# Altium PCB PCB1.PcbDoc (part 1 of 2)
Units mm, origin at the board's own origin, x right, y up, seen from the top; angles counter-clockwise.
Board outline 100 x 72 mm, 4 copper layers (Top Layer, Ground, Power, Bottom Layer), stack 1.562 mm thick; 122 components, 105 nets, 454 pads, 324 vias.
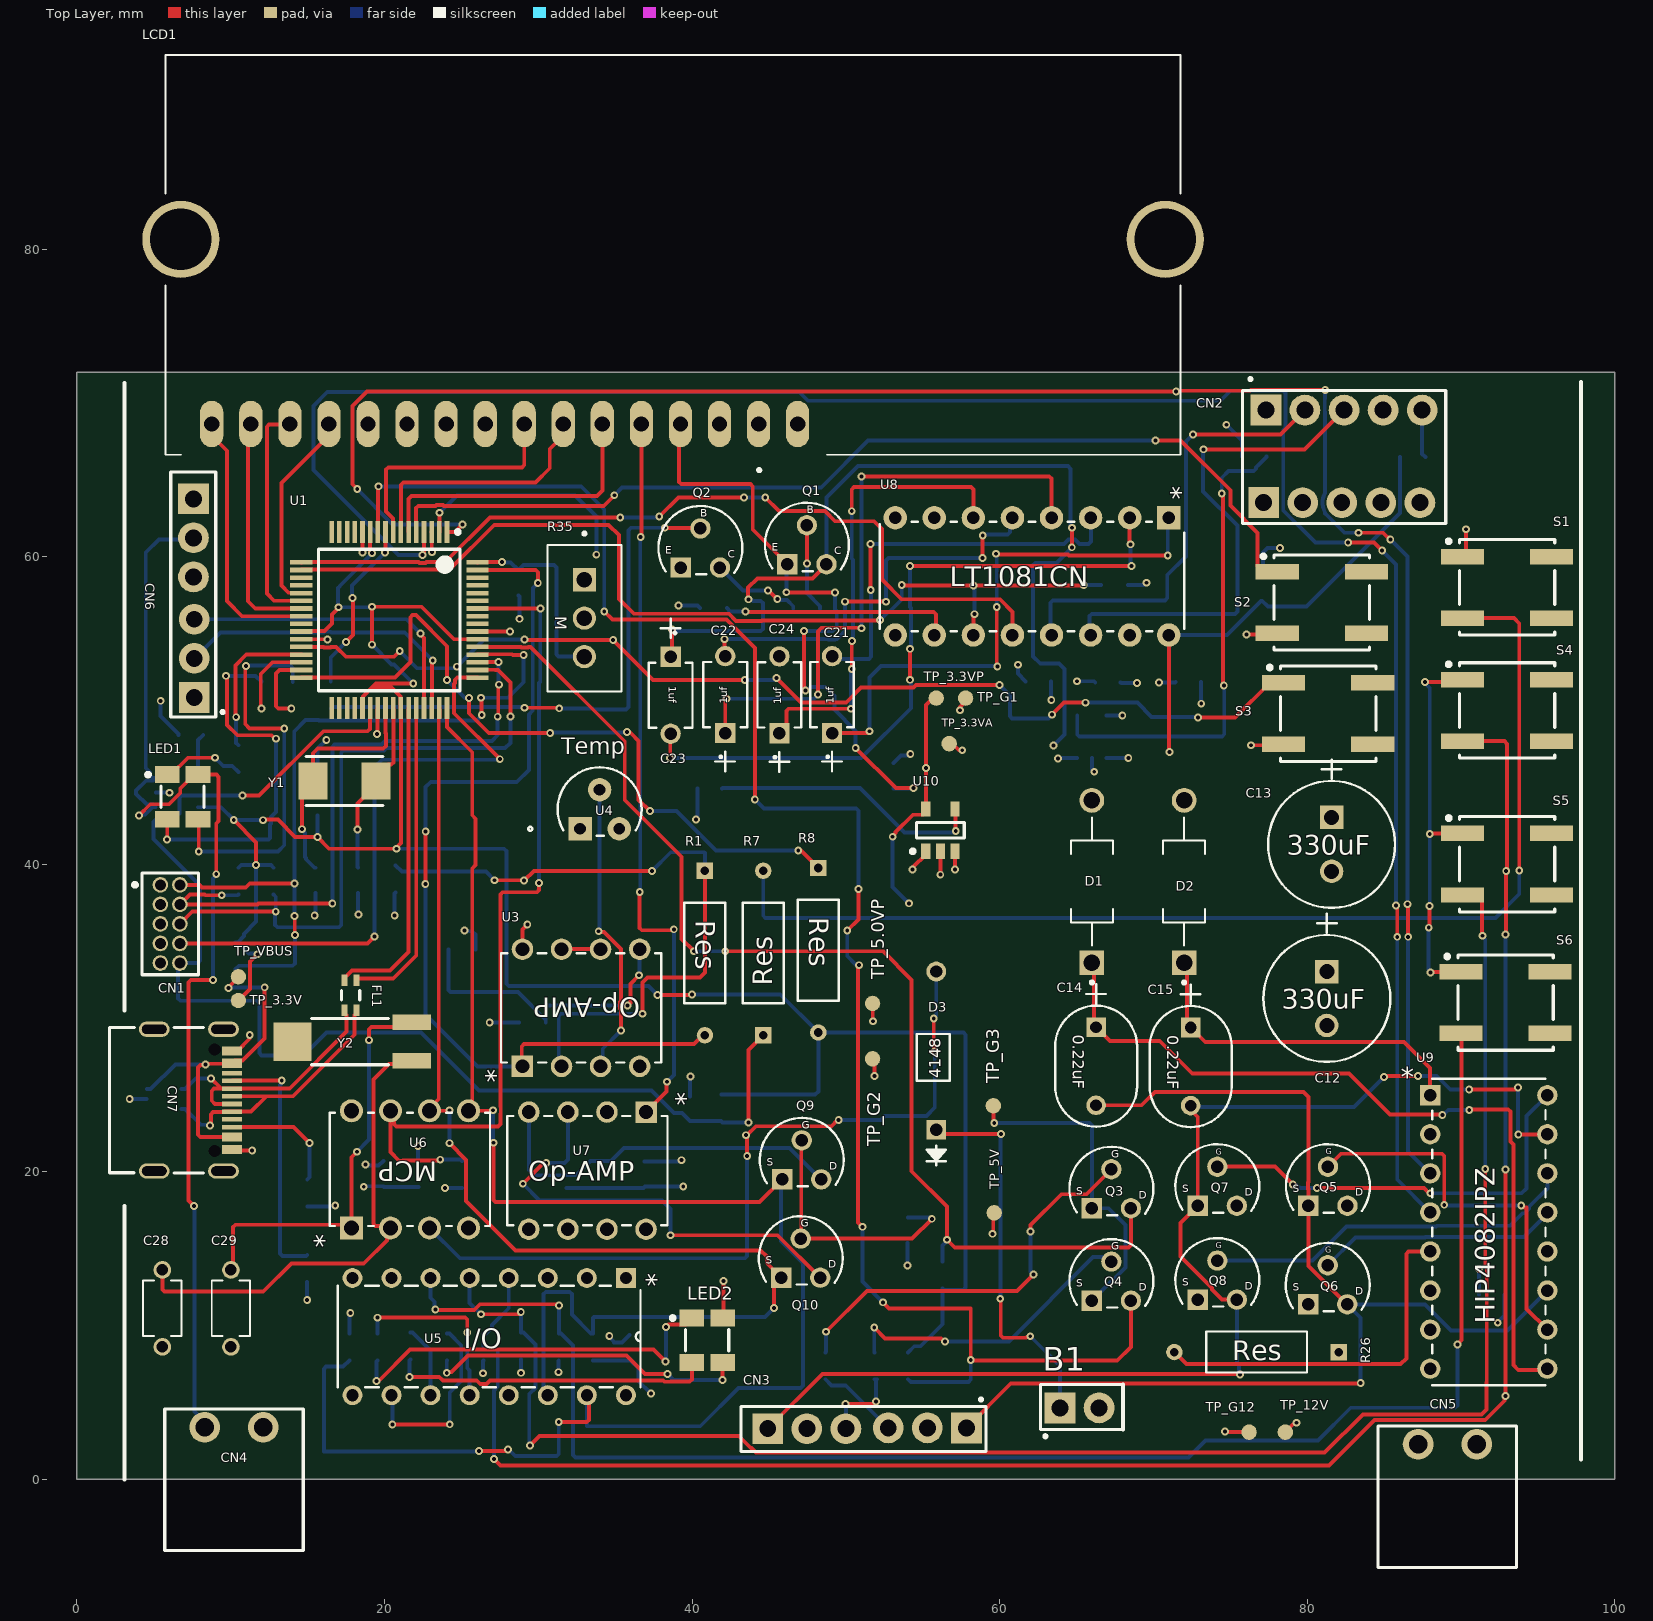
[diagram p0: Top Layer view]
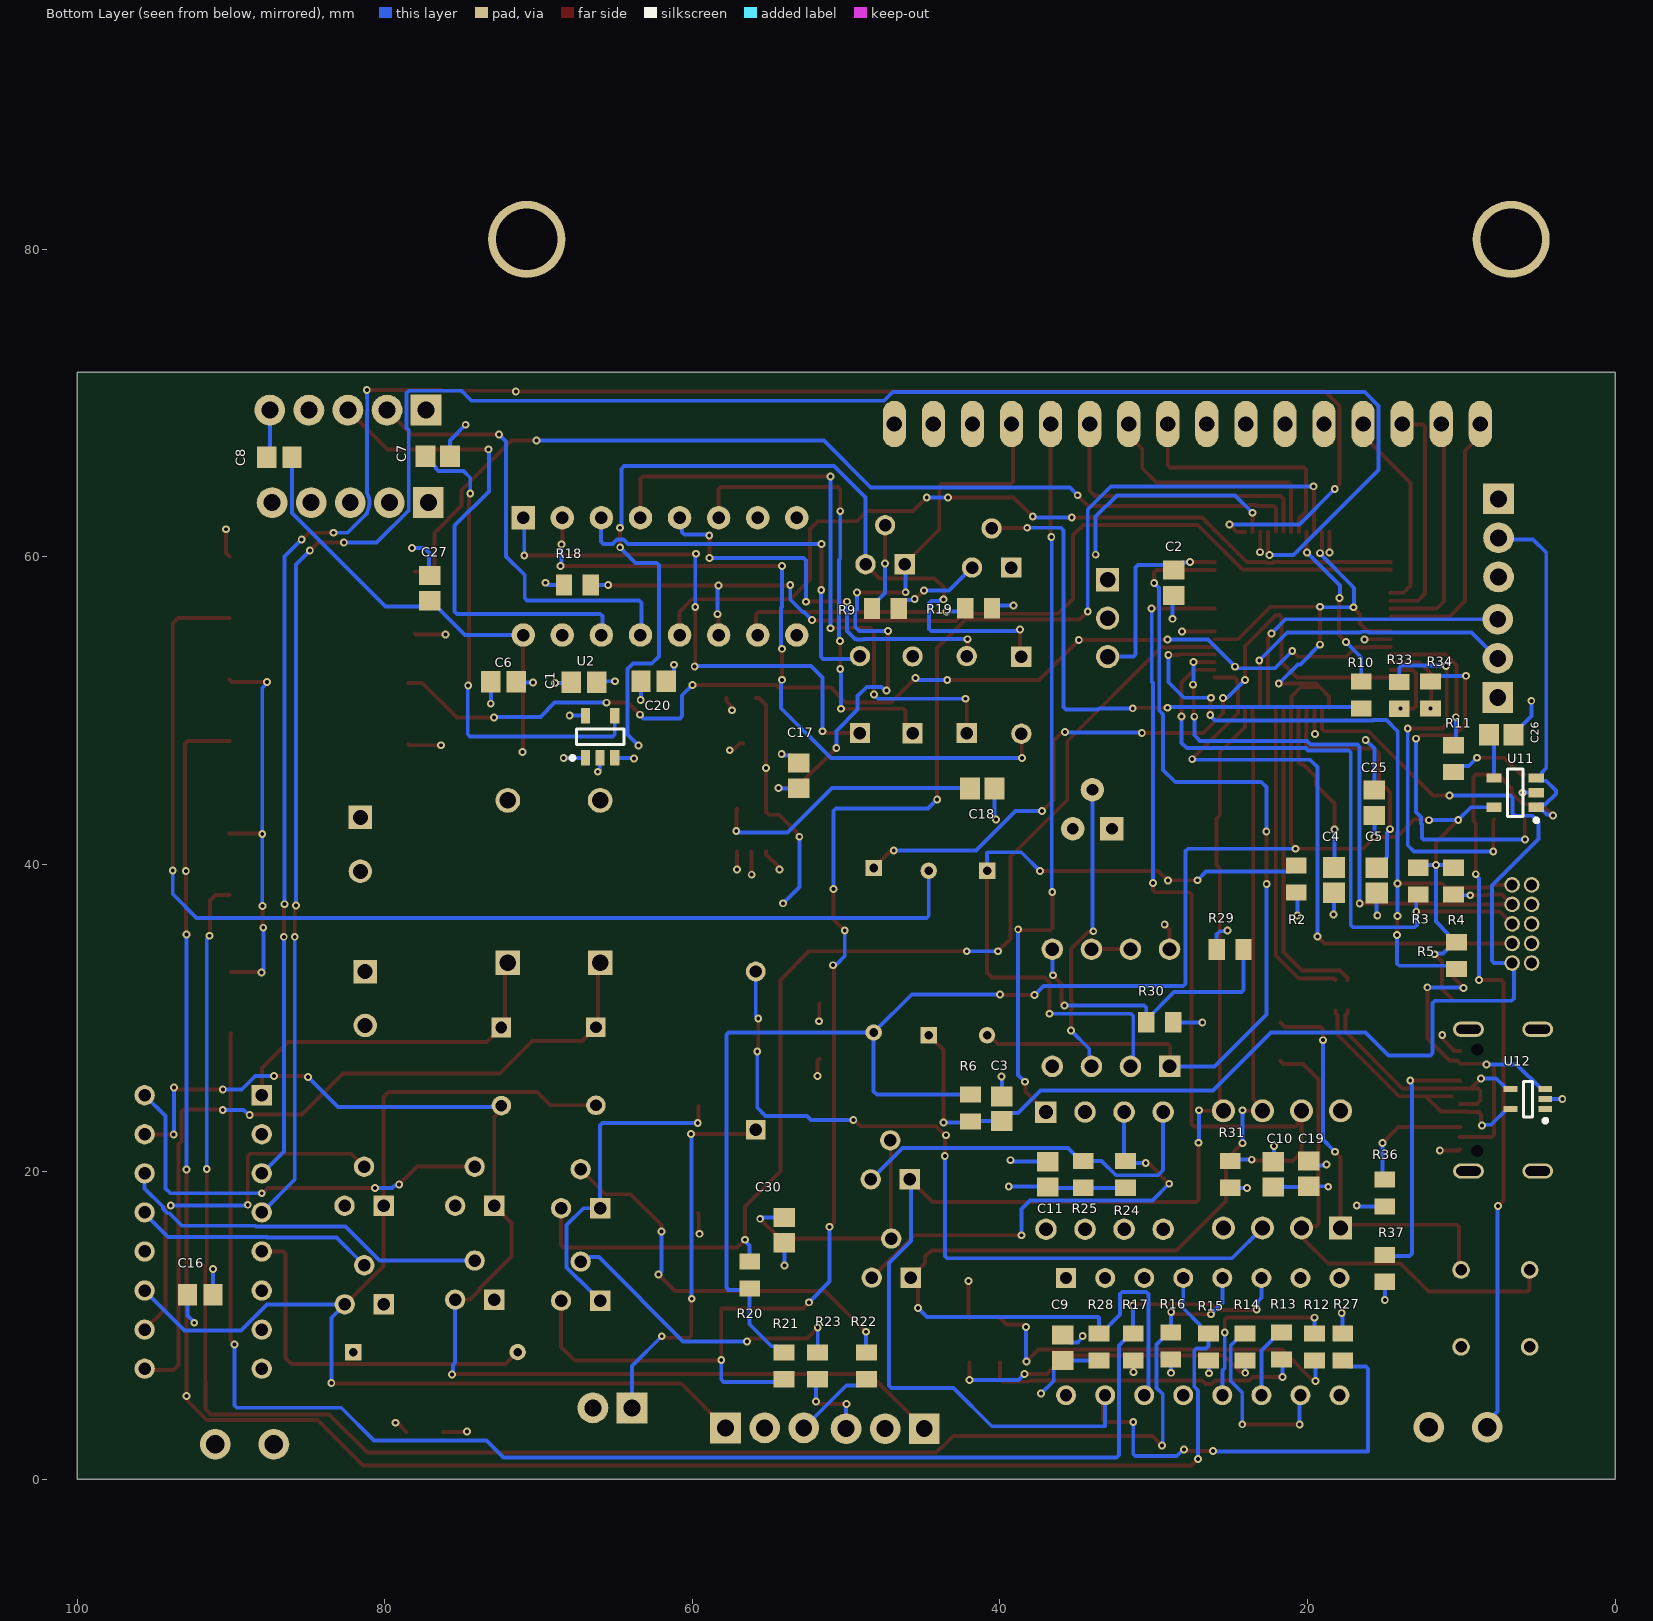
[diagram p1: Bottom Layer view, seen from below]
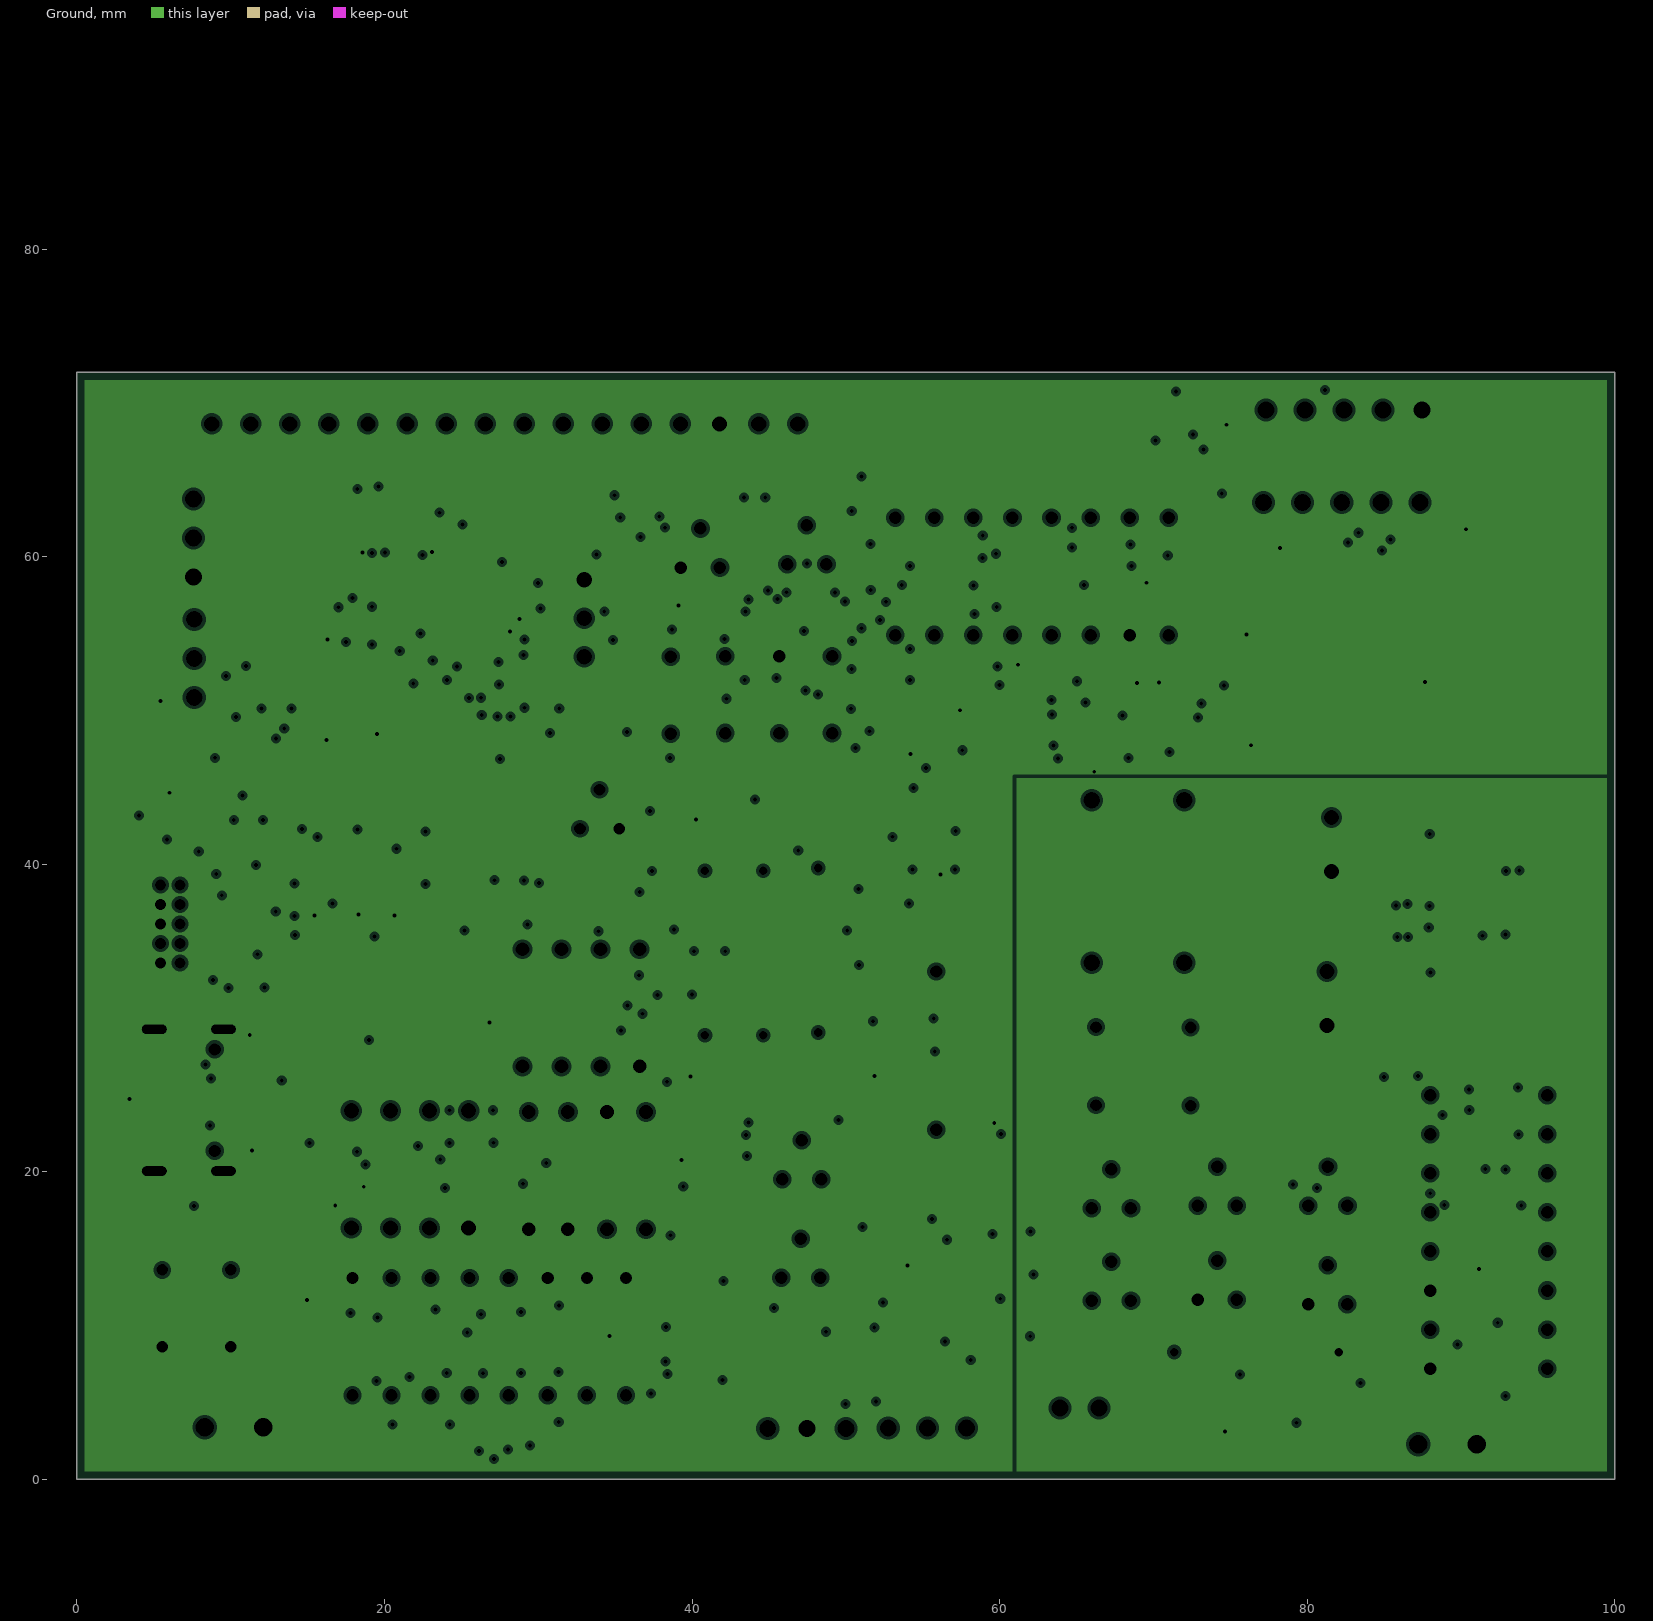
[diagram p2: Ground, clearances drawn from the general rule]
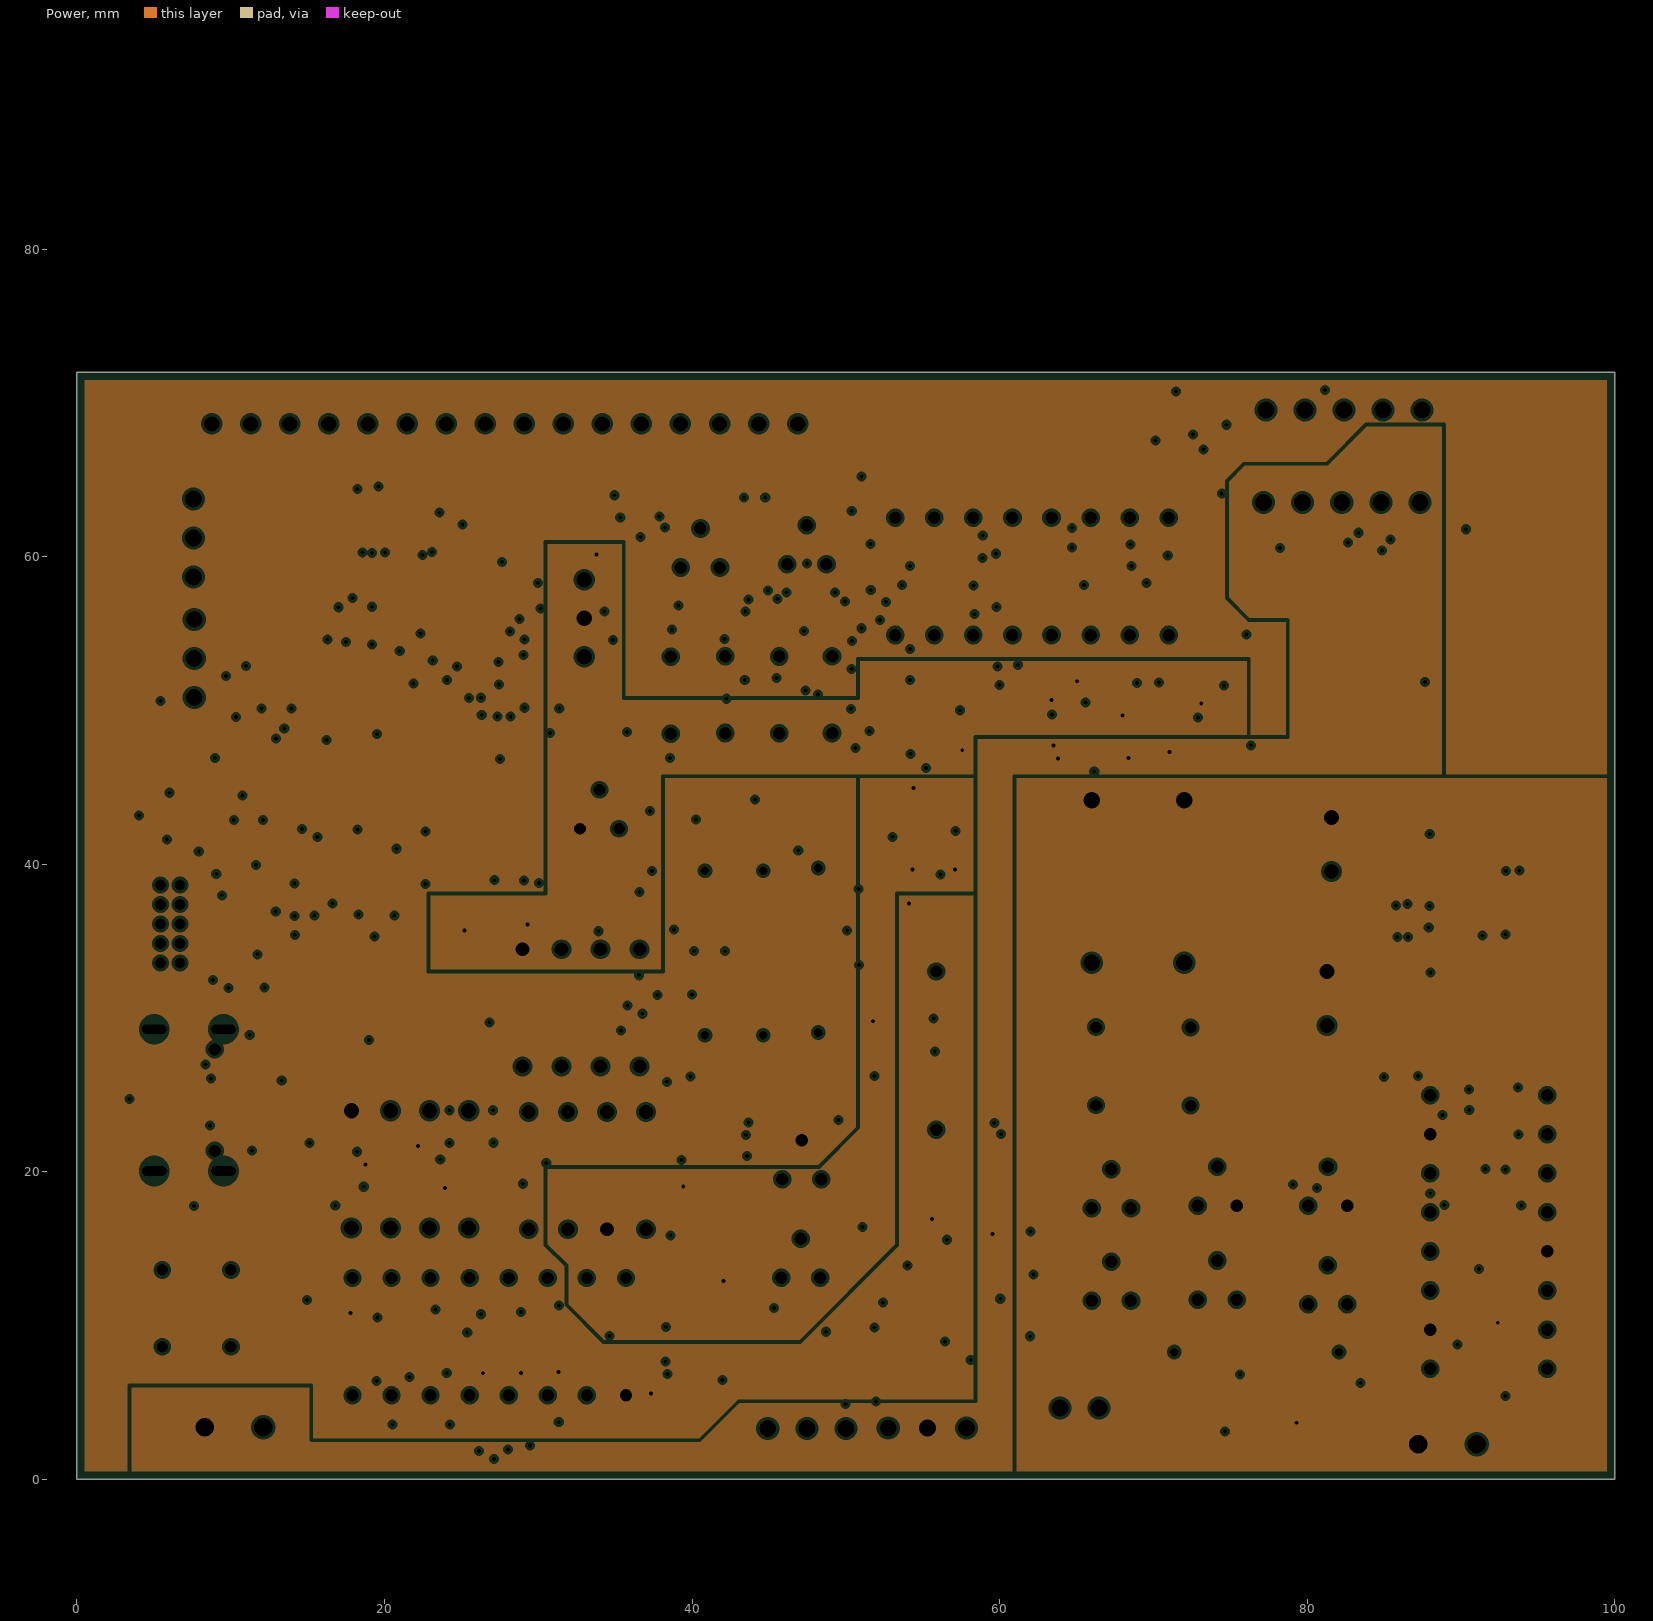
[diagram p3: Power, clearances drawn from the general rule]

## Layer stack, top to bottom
Top Solder: solder mask 0.0254, SM-001, Dk 4
Top Layer: signal copper 0.035
Prepreg 1: prepreg 0.3556, 185HR, Dk 4.31
Ground: plane copper 0.035, net (Multiple Nets)
Core: core 0.7112, 185HR, Dk 4.31
Power: plane copper 0.035, net (Multiple Nets)
Prepreg 2: prepreg 0.3556, 185HR, Dk 4.31
Bottom Layer: signal copper 0.035
Bottom Solder: solder mask 0.0254, SM-001, Dk 4

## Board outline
0,0 0,72 100,72 100,0

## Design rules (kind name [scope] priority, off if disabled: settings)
Clearance [All] p1: gap=0.127 ignorepadtopadclearanceinfootprint=TRUE
Clearance Clearance_CHGND [InNet('CHGND') vs Not InComponent (R20) AND Not InNet('CHGND')] p2: gap=1 ignorepadtopadclearanceinfootprint=TRUE
DiffPairsRouting [All] p1: maxlimit=0.254 minlimit=0.254 mostfreqgap=0.254 toplayer_minwidth=0.254 toplayer_maxwidth=0.254 toplayer_prefwidth=0.254 bottomlayer_minwidth=0.254 bottomlayer_maxwidth=0.254 bottomlayer_prefwidth=0.254 maxuncoupledlength=12.7
HoleSize [All] p1: absolutevalues=TRUE maxlimit=12.7 minlimit=0.203 maxpercent=80.000 minpercent=20.000
HoleToHoleClearance [All] p1: gap=0.25 allowstackedmicrovias=TRUE
MinimumSolderMaskSliver [All] p1: minsoldermaskwidth=0.127
PlaneClearance PlaneClearance_HV [InComponent('K1') Or InComponent('K2') Or InComponent('CN14') Or InComponent('CN15') Or InComponent('CN16') Or InComponent('CN17') Or InComponent('CN18') Or InComponent('CN19')] p1: clearance=1
PlaneClearance [All] p2: clearance=0.2
PlaneConnect PlaneConnect_Supply [InComponent('CN11')] p1: pad.planeconnectstyle=Direct pad.reliefexpansion=0.508 pad.reliefentries=4 pad.reliefconductorwidth=0.254 pad.reliefairgap=0.254 via.planeconnectstyle=Relief via.reliefexpansion=0.508 via.reliefentries=4 via.reliefconductorwidth=0.254 via.reliefairgap=0.254
PlaneConnect PlaneConnect_Servo [InNet('+5.0VSRV') OR InComponent('CN4')] p2: pad.planeconnectstyle=Direct pad.reliefexpansion=0.508 pad.reliefentries=4 pad.reliefconductorwidth=0.254 pad.reliefairgap=0.254 via.planeconnectstyle=Relief via.reliefexpansion=0.508 via.reliefentries=4 via.reliefconductorwidth=0.254 via.reliefairgap=0.254
PlaneConnect [All] p3: pad.planeconnectstyle=Relief pad.reliefexpansion=0.25 pad.reliefentries=4 pad.reliefconductorwidth=0.5 pad.reliefairgap=0.125 via.planeconnectstyle=Direct via.reliefexpansion=0.254 via.reliefentries=4 via.reliefconductorwidth=0.254 via.reliefairgap=0.127
PolygonConnect PolygonConnect_CHGND [InNet('CHGND')] p1: connectstyle=Direct reliefconductorwidth=0.254 reliefentries=4 polygonreliefangle="90 Angle" airgapwidth=0.254
PolygonConnect [All] p2: thpad.connectstyle=Relief thpad.reliefconductorwidth=0.254 thpad.reliefentries=4 thpad.polygonreliefangle="90 Angle" thpad.airgapwidth=0.254 smdpad.connectstyle=Relief smdpad.reliefconductorwidth=0.254 smdpad.reliefentries=4 smdpad.polygonreliefangle="90 Angle" smdpad.airgapwidth=0.254 via.connectstyle=Direct via.reliefconductorwidth=0.254 via.reliefentries=4 via.polygonreliefangle="90 Angle" via.airgapwidth=0.254
RoutingCorners [All] p1: cornerstyle=45-Degree minsetback=1.27 maxsetback=1.27
RoutingVias [All] p1: holewidth=0.254 width=0.508 viastyle="Through Hole" minholewidth=0.254 minwidth=0.508 maxholewidth=2.254 maxwidth=1.8
SilkToSilkClearance [All] p1: silktosilkclearance=0.003
SilkToSolderMaskClearance [IsPad] p1: minsilkscreentomaskgap=0.003 clearancetoexposedcopper=TRUE
SolderMaskExpansion ViaSolderMaskExpansion [IsVia] p1: expansion=0.051 istentingtop=TRUE
SolderMaskExpansion PadSolderMaskExpansion [IsPad] p2: expansion=0 istentingtop=FALSE
SupplyNets "Schematic Supply Nets_14" [InNet('3.3VP')] p1: voltage=0.000
SupplyNets "Schematic Supply Nets_13" [InNet('+3.3V')] p2: voltage=0.000
SupplyNets "Schematic Supply Nets_12" [InNet('+12V')] p3: voltage=0.000
SupplyNets "Schematic Supply Nets_11" [InNet('GND_12')] p4: voltage=0.000
SupplyNets "Schematic Supply Nets_10" [InNet('+5.0VP')] p5: voltage=0.000
SupplyNets "Schematic Supply Nets_7" [InNet('VBUS')] p6: voltage=0.000
SupplyNets "Schematic Supply Nets_6" [InNet('GND')] p7: voltage=0.000
SupplyNets "Schematic Supply Nets_4" [InNet('+5.0V')] p8: voltage=0.000
SupplyNets "Schematic Supply Nets" [InNet('+3.3VA')] p9: voltage=0.000
Width [All] p1: maxlimit=2.4 minlimit=0.178 preferedwidth=0.254
21 further rules are at their usual default settings.

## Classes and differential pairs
component class Sheet2: C12 C13 C14 C15 C16 CN5 CN7 D1 D2 FL1 R26 R36 R37 TP_12V TP_G12 TP_VBUS U9 U12
component class Sheet1: B1 C9 C10 C11 C17 C18 C19 C21 C22 C23 C24 C28 C29 C30 CN2 CN3 CN6 D3 LED2 Q3 Q4 Q9 Q10 R12 R13 R14 R15 R16 R17 R18 R19 R20 R21 R22 R23 R24 R25 R27 R28 R31 S4 S5 S6 TP_3.3VP TP_5.0VP U5 U6 U7 U8 U10 Y2
component class SCH001: C1 C2 C3 C4 C5 C6 C7 C8 C20 C25 C26 C27 CN1 CN4 LCD1 LED1 Q1 Q2 R1 R2 R3 R4 R5 R6 R7 R8 R9 R10 R11 R29 R30 R33 R34 R35 S1 S2 S3 TP_3.3V TP_3.3VA TP_5V TP_G1 TP_G2 TP_G3 U1 U2 U3 U4 U11 Y1
differential pair USBD1: +USBD1_P -USBD1_N
differential pair USBD0: +USBD0_P -USBD0_N

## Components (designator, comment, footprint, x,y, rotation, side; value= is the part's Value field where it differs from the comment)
B1 "BATTERY" BAT 66.493,4.629 r0 top
C1 "0.1µF" CAPC2012X14N 67.047,51.817 r0 bottom
C2 "0.1µF" CAPC2012X14N 28.707,58.301 r270 bottom
C3 "0.01µF" CAPC2012X08N 39.879,24.102 r90 bottom
C4 "10pF" CAPC2012X09N 18.276,38.961 r270 bottom
C5 "10pF" CAPC2012X09N 15.503,38.946 r270 bottom
C6 "0.1µF" CAPC2012X14N 72.282,51.865 r180 bottom
C7 "0.01µF" CAPC2012X08N 76.566,66.521 r180 bottom
C8 "1µF" CAPC2012X14N 86.859,66.473 r0 bottom
C9 "0.1µF" CAPC2012X14N 35.932,8.559 r90 bottom
C10 "0.1µF" CAPC2012X14N 22.216,19.832 r270 bottom
C11 "0.1µF" CAPC2012X14N 36.905,19.832 r90 bottom
C12 "330uF" PCAP_8X112_PAN 81.28,33.02 r270 top
C13 "330uF" PCAP_8X112_PAN 81.589,43.04 r270 top
C14 "0.22uF" C330C224K1R5TA 66.021,26.737 r270 top
C15 "0.22uF" C330C224K1R5TA 72.17,26.713 r270 top
C16 "1µF" CAPC2012X14N 92,12 r180 bottom
C17 "1µF" CAPC2012X14N 53.099,45.756 r90 bottom
C18 "0.01µF" CAPC2012X08N 41.153,44.922 r180 bottom
C19 "0.1µF" CAPC2012X14N 19.93,19.882 r270 bottom
C20 "0.1µF" CAPC2012X14N 62.522,51.891 r180 bottom
C21 "1uF" TAP105M035SCS 49.099,48.542 r90 top
C22 "1uF" TAP105M035SCS 42.153,48.542 r90 top
C23 "1uF" TAP105M035SCS 38.611,53.472 r270 top
C24 "1uF" TAP105M035SCS 45.678,48.524 r90 top
C25 "0.1µF" CAPC2012X14N 15.652,43.998 r90 bottom
C26 "0.01µF" CAPC2012X08N 7.415,48.409 r180 bottom
C27 "1µF" CAPC2012X14N 77.08,57.95 r90 bottom
C28 "5pF" RCE5C1H5R0C0M1H03A 5.56,11.117 r270 top
C29 "5pF" RCE5C1H5R0C0M1H03A 10.019,11.117 r270 top
C30 "0.1µF" CAPC2012X14N 54.029,16.207 r270 bottom
CN1 "GRPB052VWVN-RC" SULLINS_GRPB052VWVN-RC 6.067,36.115 r270 top
CN2 "CONN D-SUB PLUG 9POS PNL MNT" DEP9 79.865,69.509 r0 top
CN3 "180SH-EN" 6_PIN_MALE 55.276,3.362 r180 top
CN4 "1803277" PHOENIX_1803277 10.216,3.38 r0 top
CN5 "1803277" PHOENIX_1803277 89.12,2.28 r0 top
CN6 "BLE" 6_PIN_MALE 7.648,53.41 r90 top
CN7 "2171800001" MOLEX_2171800001 5.032,24.657 r270 top
D1 "Diode" UF4002 66,39 r90 top
D2 "Diode" UF4002 72,39 r90 top
D3 "4148" 1N4148 55.88,22.733 r90 top
FL1 "ACM2012-900-2P-T001" LITTELFUSE_ACM2012-900-2P-T001 17.793,31.477 r270 top
LCD1 "LCD MOD 32 DIG 16 X 2 REFLECTIVE" LCM-S01602DTR/M 39.276,79.753 r0 top
LED1 "RGB" WURTH_150121M153000 6.877,44.375 r0 top
LED2 "RGB" WURTH_150121M153000 40.987,9.037 r0 top
Q1 "2N3904BU" 2N3904BU 46.2,59.505 r0 top
Q2 "2N3904BU" 2N3904BU 39.276,59.292 r0 top
Q3 "ZVNL120A" ZVNL120A 66,17.625 r0 top
Q4 "ZVNL120A" ZVNL120A 66,11.62 r0 top
Q5 "VN2210N3-G" VN2210N3-G 80.072,17.856 r0 top
Q6 "VN2210N3-G" VN2210N3-G 80.059,11.444 r0 top
Q7 "VN2210N3_G2" VN2210_2 72.921,17.752 r0 top
Q8 "VN2210N3_G2" VN2210_2 72.921,11.647 r0 top
Q9 "ZVNL120A" ZVNL120A 45.865,19.505 r0 top
Q10 "ZVNL120A" ZVNL120A 45.8,13.115 r0 top
R1 "56K" TH_RES 40.838,39.577 r270 top
R2 "10.0k" RESC2012X06N 20.73,39.039 r90 bottom
R3 "10.0k" RESC2012X06N 12.797,38.893 r270 bottom
R4 "10.0k" RESC2012X06N 10.502,38.893 r270 bottom
R5 "10.0k" RESC2012X06N 10.318,34.05 r90 bottom
R6 "10.0k" RESC2012X06N 41.914,24.147 r90 bottom
R7 "470" TH_RES 44.63,28.877 r90 top
R8 "1M" TH_RES 48.214,39.755 r270 top
R9 "1.2K" RESC2012X06N 47.456,56.625 r0 bottom
R10 "4.42k" RESC2012X06N 16.509,51 r270 bottom
R11 "750" RESC2012X06N 10.502,46.862 r270 bottom
R12 "750" RESC2012X06N 19.541,8.609 r270 bottom
R13 "750" RESC2012X06N 21.686,8.676 r270 bottom
R14 "750" RESC2012X06N 24.067,8.611 r270 bottom
R15 "10.0k" RESC2012X06N 26.44,8.611 r270 bottom
R16 "10.0k" RESC2012X06N 28.89,8.676 r270 bottom
R17 "10.0k" RESC2012X06N 31.335,8.609 r270 bottom
R18 "4.42k" RESC2012X06N 67.484,58.155 r180 bottom
R19 "4.42k" RESC2012X06N 41.386,56.65 r0 bottom
R20 "4.42k" RESC2012X06N 56.279,13.291 r270 bottom
R21 "4.42k" RESC2012X06N 54.052,7.383 r90 bottom
R22 "4.42k" RESC2012X06N 48.672,7.383 r90 bottom
R23 "4.42k" RESC2012X06N 51.872,7.383 r90 bottom
R24 "4.42k" RESC2012X06N 31.838,19.832 r270 bottom
R25 "4.42k" RESC2012X06N 34.586,19.832 r270 bottom
R26 "15K" TH_RES 82.064,8.276 r180 top
R27 "4.42k" RESC2012X06N 17.715,8.609 r90 bottom
R28 "4.42k" RESC2012X06N 33.567,8.609 r270 bottom
R29 "10.0k" RESC2012X06N 25.033,34.45 r0 bottom
R30 "10.0k" RESC2012X06N 29.611,29.715 r0 bottom
R31 "4.42k" RESC2012X06N 25.033,19.832 r270 bottom
R33 "750" RESC2012X06N 14.034,50.979 r90 bottom
R34 "750" RESC2012X06N 12,51 r90 bottom
R35 "10K" PV36W103C01B00 33,56 r270 top
R36 "5.10k" RESC2012X06N 14.979,18.624 r90 bottom
R37 "5.10k" RESC2012X06N 14.979,13.722 r90 bottom
S1 "KSC241JLFS" CK_KSC241JLFS 93,58 r0 top
S2 "KSC241JLFS" CK_KSC241JLFS 80.955,57.015 r0 top
S3 "KSC241JLFS" CK_KSC241JLFS 81.366,49.79 r0 top
S4 "KSC241JLFS" CK_KSC241JLFS 93,50 r0 top
S5 "KSC241JLFS" CK_KSC241JLFS 93,40 r0 top
S6 "KSC241JLFS" CK_KSC241JLFS 92.9,31 r0 top
TP_3.3V "Test Point" TP100 10.502,31.136 r270 top
TP_3.3VA "Test Point" TP100 56.721,47.84 r90 top
TP_3.3VP "Test Point" TP100 55.88,50.8 r90 top
TP_5.0VP "Test Point" TP100 51.74,30.946 r90 top
TP_5V "Test Point" TP100 59.648,17.331 r90 top
TP_12V "Test Point" TP100 78.579,3.068 r90 top
TP_G1 "Test Point" TP100 57.79,50.8 r90 top
TP_G2 "Test Point" TP100 51.74,27.344 r90 top
TP_G3 "Test Point" TP100 59.595,24.291 r90 top
TP_G12 "Test Point" TP100 76.224,3.068 r90 top
TP_VBUS "Test Point" TP100 10.502,32.679 r90 top
U1 "TM4C1233H6PMI" TSQFP50P1200X1200X160-64N 20.32,55.88 r270 top
U2 "TPS73233DBVT" SOT95P280X145-5N 66,48.286 r90 bottom
U3 "IC OPAMP GP 200KHZ RRO 8DIP" LT1490CN8 29.026,26.867 r90 top
U4 "TMP35GT9Z" TMP35GT9Z 32.752,42.309 r0 top
U5 "IC XPNDR 100KHZ I2C 16SOIC" PCF8574AN 35.569,13.069 r270 top
U6 "MCP7940N" MCP7940N-I/P 17.851,16.346 r90 top
U7 "MAX518BCPA+" LT1490CN8 36.956,23.867 r270 top
U8 "IC DVR/RCVR DUAL-RS232 5V 16-DIP" LT1081CN 70.996,62.522 r270 top
U9 "HIP4082IPZ" HIP4082IPZ 88,24.977 r0 top
U10 "TPS73233DBVT" SOT95P280X145-5N 56.153,42.216 r90 top
U11 "TPS73233DBVT" SOT95P280X145-5N 6.502,44.652 r0 bottom
U12 "SP3003-02JTG" SOT65P220X110-5N 5.667,24.723 r0 bottom
Y1 "16 MHz" ABRACON_ABM3 17.4,45.403 r0 top
Y2 "32.768 kHz" ABRACON_AB26TRB 21.771,28.461 r90 top

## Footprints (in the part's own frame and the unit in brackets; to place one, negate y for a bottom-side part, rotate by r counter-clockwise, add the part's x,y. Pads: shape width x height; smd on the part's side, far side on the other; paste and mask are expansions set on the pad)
1N4148 [mil]
  rect 51x51 hole 31 paste-99999 mask+0: 1(0,0)
  round 51 hole 31 paste-99999 mask+0: 2(405,0)
  silkscreen extent -90,-35 245,50
2N3904BU [mil]
  rect 52x52 hole 32 paste-99999 mask+0: 1(0,0)
  round 52 hole 32 paste-99999 mask+0: 2(50,100) 3(100,0)
  silkscreen extent -57,-18 158,157, body extent -52,-11 152,152, height 290
6_PIN_MALE [mm]
  rect 2x2 hole 1.1: 1(-2.565,0.017) 6(10.35,0.065)
  round 2 hole 1.1: 2(-0.025,0.017) 3(2.515,0.017) 4(5.27,0.065) 5(7.81,0.065)
  silkscreen extent -3.83,-1.93 12.1,1.55, body extent -3.96,-1.25 11.75,1.35, height 8.41
ABRACON_AB26TRB [mm] "Low Frequency Reflowable Cylindrical Watch Crystal"
  rect 2.5x2.5 smd: 0(0,7.75)
  rect 1x2.5 smd: 1(-1.25,0) 2(1.25,0)
  silkscreen extent -1.5,1.5 1.5,6.5, body extent -1.42,-1 1.42,8, height 2.25
ABRACON_ABM3 [mm] "Ceramic SMD Crystal"
  rect 1.9x2.4 smd: 1(-2.05,0) 2(2.05,0)
  silkscreen extent -2.5,-1.6 2.5,1.6, body extent -2.5,-1.6 2.5,1.6, height 1.35
BAT [mm]
  rect 2x2 hole 1.1: 1(-2.565,0.017)
  round 2 hole 1.1: 2(-0.025,0.017)
  silkscreen extent -3.83,-1.93 1.52,1.55
C330C224K1R5TA [mil] "0.22 µF ±10% 100V Ceramic Capacitor X7R Radial"
  rect 50x50 hole 30 paste-99999 mask-25: 1(-105,10)
  round 50 hole 30 paste-99999 mask-25: 2(95,10)
  silkscreen extent -215,-95 150,115, body extent -165,-75 135,125, height 410
CAPC2012X08N [mm] "Chip Capacitor, 2-Leads, Body 2.00x1.25mm, IPC Medium Density"
  rect 1.3x1.4 smd: 1(-0.8,0) 2(0.8,0)
  body extent -1.05,-0.67 1.05,0.67, height 0.75
CAPC2012X09N [mm] "Chip Capacitor, 2-Leads, Body 2.00x1.25mm, IPC Medium Density"
  rect 1.35x1.45 smd: 1(-0.825,0) 2(0.825,0)
  body extent -1.1,-0.72 1.1,0.72, height 0.94
CAPC2012X14N [mm] "Chip Capacitor, 2-Leads, Body 2.00x1.25mm, IPC Medium Density"
  rect 1.25x1.4 smd: 1(-0.825,0) 2(0.825,0)
  body extent -1.05,-0.67 1.05,0.67, height 1.35
CK_KSC241JLFS [mm] "KSC2 Series Sealed Tact Switch for SMT"
  rect 2.8x1 smd: 1(-2.9,2) 2(-2.9,-2) 3(2.9,-2) 4(2.9,2)
  silkscreen extent -3.92,-3.1 3.1,3.12, body extent -3.4,-3.15 3.4,3.15, height 3.55
DEP9 [mm]
  rect 2x2 hole 1.1: 1(-2.548,0.023) 6(-2.696,-5.997)
  round 2 hole 1.1: 2(-0.008,0.023) 3(2.532,0.023) 4(5.072,0.023) 5(7.612,0.023) 7(-0.156,-5.997) 8(2.384,-5.997) 9(4.924,-5.997) 10(7.464,-5.997)
  silkscreen extent -4.06,-7.37 9.14,2.13, body extent -3.94,-7.29 6.34,1.29, height 8.59
HIP4082IPZ [mil]
  rect 52x52 hole 32 paste-99999 mask+0: 1(0,0)
  round 52 hole 32 paste-99999 mask+0: 2(0,-100) 3(0,-200) 4(0,-300) 5(0,-400) 6(0,-500) 7(0,-600) 8(0,-700) 9(300,-700) 10(300,-600) 11(300,-500) 12(300,-400) 13(300,-300) 14(300,-200) 15(300,-100) 16(300,0)
  silkscreen extent 5,-743 295,42, body extent -5,-737 315,37, height 215
LCM-S01602DTR/M [mm]
  oval 1.508x3.016 hole 1: 1(2.512,-11.127) 2(-0.028,-11.127) 3(-2.568,-11.127) 4(-5.108,-11.127) 5(-7.648,-11.127) 6(-10.188,-11.127) 7(-12.728,-11.127) 8(-15.268,-11.127) 9(-17.808,-11.127) 10(-20.348,-11.127) 11(-22.888,-11.127) 12(-25.428,-11.127) 13(-27.968,-11.127) 14(-30.508,-11.127) 15(7.592,-11.127) 16(5.052,-11.127)
  round 5.016 hole 4: S1(31.492,0.873) S2(-32.508,0.873)
  silkscreen extent -33.51,-14.23 32.49,12.87
LITTELFUSE_ACM2012-900-2P-T001 [mm] "Common Mode Choke"
  rect 0.75x0.4 smd: 1(-0.975,0.4) 2(-0.975,-0.4) 3(0.975,-0.4) 4(0.975,0.4)
  silkscreen extent -0.3,-0.6 0.3,0.6, body extent -1,-0.6 1,0.6, height 1.21
LT1081CN [mil]
  rect 60x60 hole 32 paste-99999 mask+0: 1(0,0)
  round 60 hole 32 paste-99999 mask+0: 2(0,-100) 3(0,-200) 4(0,-300) 5(0,-400) 6(0,-500) 7(0,-600) 8(0,-700) 9(300,-700) 10(300,-600) 11(300,-500) 12(300,-400) 13(300,-300) 14(300,-200) 15(300,-100) 16(300,0)
  silkscreen extent 10,-740 290,40, body extent -5,-735 315,35, height 140
LT1490CN8 [mil]
  rect 55x55 hole 35 paste-99999 mask+0: 1(-0.56,2.06)
  round 55 hole 35 paste-99999 mask+0: 2(-0.56,-97.94) 3(-0.56,-197.94) 4(-0.56,-297.94) 5(299.44,-297.94) 6(299.44,-197.94) 7(299.44,-97.94) 8(299.44,2.06)
  silkscreen extent 9,-353 289,57, body extent -5,-350 315,50, height 160
MCP7940N-I/P [mil]
  rect 59x59 hole 39 paste-99999 mask+0: 1(0,0)
  round 59 hole 39 paste-99999 mask+0: 2(0,-100) 3(0,-200) 4(0,-300) 5(300,-300) 6(300,-200) 7(300,-100) 8(300,0)
  silkscreen extent 5,-355 295,55, body extent -5,-350 315,50, height 215
MOLEX_2171800001 [mm]
  round 0.4 hole 0.8 unplated: 0(-3.3,3.94) 0(3.3,3.94)
  oval 1x2 hole 0.6 slot 1.6 at 90 deg: 1(-4.61,4.5) 1(-4.61,0) 1(4.61,4.5) 1(4.61,0)
  rect 0.6x1.3 smd: A1B12(-3.2,5.06) A4B9(-2.4,5.06) B1A12(3.2,5.06) B4A9(2.4,5.06)
  rect 0.3x1.3 smd: A5(-1.25,5.06) A6(-0.25,5.06) A7(0.25,5.06) A8(1.25,5.06) B5(1.75,5.06) B6(0.75,5.06) B7(-0.75,5.06) B8(-1.75,5.06)
  silkscreen extent -4.73,-2.91 4.73,3.2, body extent -4.73,-2.9 4.74,5.5, height 7.79
PCAP_8X112_PAN [mil]
  rect 60x60 hole 38 paste-99999 mask+0: 1(0,0)
  round 60 hole 38 paste-99999 mask+0: 2(138,0)
  silkscreen extent -148,-162 231,162, body extent -89,-158 228,158, height 454
PCF8574AN [mil]
  rect 51x51 / inner round 60 / far side rect 51x51 hole 31 paste-99999 mask-25.5: 1(-0.87,5.18)
  round 51 / inner round 60 / far side round 51 hole 31 paste-99999 mask-25.5: 2(-0.87,-94.82) 3(-0.87,-194.82) 4(-0.87,-294.82) 5(-0.87,-394.82) 6(-0.87,-494.82) 7(-0.87,-594.82) 8(-0.87,-694.82) 9(299.13,-694.82) 10(299.13,-594.82) 11(299.13,-494.82) 12(299.13,-394.82) 13(299.13,-294.82) 14(299.13,-194.82) 15(299.13,-94.82) 16(299.13,5.18)
  silkscreen extent 19,-732 279,43, body extent -11,-722 309,53, height 205
PHOENIX_1803277 [mm] "PCB header - MC 1,5/ 2-G-3,81"
  round 2 hole 1.2: 1(-1.905,0) 2(1.905,0)
  silkscreen extent -4.5,-8 4.5,1.2, body extent -4.5,-8 4.5,1.3, height 7.25
PV36W103C01B00 [mm]
  rect 1.508x1.508 / inner round 1.508 / far side rect 1.508x1.508 hole 1: 1(-2.5,0)
  round 1.508 hole 1: 2(0,0) 3(2.5,0)
  silkscreen extent -5.6,-2.41 4.76,2.42, body extent -4.76,-2.41 4.76,2.42, height 11.55
RCE5C1H5R0C0M1H03A [mm] "5 pF ±0.25pF 50V Ceramic Capacitor C0G, NP0 Radial"
  round 1.15 hole 0.75: 1(-2.5,0) 2(2.5,0)
  silkscreen extent -1.8,-1.25 1.8,1.25
RESC2012X06N [mm] "Chip Resistor, 2-Leads, Body 2.00x1.25mm, IPC Medium Density"
  rect 1.05x1.35 smd: 1(-0.875,0) 2(0.875,0)
  body extent -1.05,-0.67 1.05,0.67, height 0.6
SOT65P220X110-5N [mm] "SOT23, 5-Leads, Body 2.05x2.20mm, Pitch 0.65mm, IPC Medium Density"
  rect 0.9x0.4 smd: 1(-1.125,0.65) 2(-1.125,0) 3(-1.125,-0.65) 4(1.125,-0.65) 5(1.125,0.65)
  silkscreen extent -1.25,-1.15 0.3,1.52, body extent -1.2,-1.12 1.2,1.12, height 1.1
SOT95P280X145-5N [mm] "SOT23, 5-Leads, Body 2.90x2.80mm, Pitch 0.95mm, IPC Medium Density"
  rect 1x0.6 smd: 1(-1.375,0.95) 2(-1.375,0) 3(-1.375,-0.95) 4(1.375,-0.95) 5(1.375,0.95)
  silkscreen extent -1.5,-1.55 0.5,1.93, body extent -1.5,-1.53 1.5,1.53, height 1.45
SULLINS_GRPB052VWVN-RC [mil] "CONN HEADER VERT 10POS 1.27MM"
  round 40 hole 28: 1(-100,-25) 2(-100,25) 3(-50,-25) 4(-50,25) 5(0,-25) 6(0,25) 7(50,-25) 8(50,25) 9(100,-25) 10(100,25)
  silkscreen extent -130,-95 130,72, body extent -125,-68 125,68, height 154
TAP105M035SCS [mil]
  rect 52x52 hole 32 paste-99999 mask+0: 1(-0.55,-0.19)
  round 52 hole 32 paste-99999 mask+0: 2(196.3,-0.19)
  silkscreen extent -98,-56 181,56, body extent -21,-47 220,55, height 308
TH_RES [mil]
  rect 42x42 hole 22 paste-99999 mask+0: 1(0,0)
  round 42 hole 22 paste-99999 mask+0: 2(421.26,0)
  silkscreen extent 82,-52 340,53, body extent -6,-47 427,47, height 95
TMP35GT9Z [mil]
  rect 60x60 hole 30 paste-99999 mask+0: 1(-1.25,-0.24)
  round 60 hole 30 paste-99999 mask+0: 2(48.75,99.76) 3(98.75,-0.24)
  silkscreen extent -134,-18 156,157, body extent -54,-10 151,152, height 290
TP100 [mm] "Surface Mount Test Point"
  round 1 smd: 1(0,0)
TSQFP50P1200X1200X160-64N [mm] "TSQFP, 64-Leads, Body 10.00x10.00mm, Pitch 0.50mm, IPC Medium Density"
  rect 1.45x0.3 smd: 1(-5.725,3.75) 2(-5.725,3.25) 3(-5.725,2.75) 4(-5.725,2.25) 5(-5.725,1.75) 6(-5.725,1.25) 7(-5.725,0.75) 8(-5.725,0.25) 9(-5.725,-0.25) 10(-5.725,-0.75) 11(-5.725,-1.25) 12(-5.725,-1.75) 13(-5.725,-2.25) 14(-5.725,-2.75) 15(-5.725,-3.25) 16(-5.725,-3.75) 33(5.725,-3.75) 34(5.725,-3.25) 35(5.725,-2.75) 36(5.725,-2.25) 37(5.725,-1.75) 38(5.725,-1.25) 39(5.725,-0.75) 40(5.725,-0.25) 41(5.725,0.25) 42(5.725,0.75) 43(5.725,1.25) 44(5.725,1.75) 45(5.725,2.25) 46(5.725,2.75) 47(5.725,3.25) 48(5.725,3.75)
  rect 0.3x1.45 smd: 17(-3.75,-5.725) 18(-3.25,-5.725) 19(-2.75,-5.725) 20(-2.25,-5.725) 21(-1.75,-5.725) 22(-1.25,-5.725) 23(-0.75,-5.725) 24(-0.25,-5.725) 25(0.25,-5.725) 26(0.75,-5.725) 27(1.25,-5.725) 28(1.75,-5.725) 29(2.25,-5.725) 30(2.75,-5.725) 31(3.25,-5.725) 32(3.75,-5.725) 49(3.75,5.725) 50(3.25,5.725) 51(2.75,5.725) 52(2.25,5.725) 53(1.75,5.725) 54(1.25,5.725) 55(0.75,5.725) 56(0.25,5.725) 57(-0.25,5.725) 58(-0.75,5.725) 59(-1.25,5.725) 60(-1.75,5.725) 61(-2.25,5.725) 62(-2.75,5.725) 63(-3.25,5.725) 64(-3.75,5.725)
  silkscreen extent -5.85,-4.6 4.6,4.6, body extent -6,-6 6,6, height 1.6
UF4002 [mm] "Diode 100 V 1A Through Hole DO-41"
  round 1.61 hole 1.07: A(5.148,0)
  rect 1.61x1.61 hole 1.07: K(-5.402,0)
  silkscreen extent -6.79,-1.36 4.02,1.36, body extent -5.83,-1.36 5.32,1.36, height 2.71
VN2210_2 [mil]
  rect 52x52 hole 32 paste-99999 mask+0: 1(-1.3,1.52)
  round 52 hole 32 paste-99999 mask+0: 2(48.7,101.52) 3(98.7,1.52)
  silkscreen extent -59,-16 156,159, body extent -54,-9 151,154, height 290
VN2210N3-G [mil]
  rect 52x52 hole 32 paste-99999 mask+0: 1(0.31,-2.57)
  round 52 hole 32 paste-99999 mask+0: 2(50.31,97.43) 3(100.31,-2.57)
  silkscreen extent -57,-20 158,155, body extent -52,-14 153,149, height 290
WURTH_150121M153000 [mm]
  rect 1.6x1.1 smd: 1(-1,1.45) 2(-1,-1.45) 3(1,-1.45) 4(1,1.45)
  silkscreen extent -2.37,-0.7 1.4,1.57, body extent -1.35,-1.6 1.35,1.6, height 1.08
ZVNL120A [mil]
  rect 52x52 hole 32 paste-99999 mask+0: 1(0,0)
  round 52 hole 32 paste-99999 mask+0: 2(50,100) 3(100,0)
  silkscreen extent -57,-18 158,157, body extent -52,-11 152,152, height 290

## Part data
C1 C2 C6 C9 C10 C11 C19 C20 C25 C30: library part UMK212B7104KGHT, "0.1µF/50V/±10% X7R Ceramic Chip Capacitor", Manufacturer="Taiyo Yuden"
C3 C7 C18 C26: library part CL21B103KBANNNC, "0.01µF/50V/±10% X7R Ceramic Chip Capacitor", Manufacturer="Samsung Electro-Mechanics"
C4 C5: library part 08051A100KAT, "10pF/100V/±10% C0G (NP0) Ceramic Chip Capacitor", Manufacturer=Kyocera/AVX
C8 C16 C17 C27: library part CL21B105KBFNNNG, "1µF/50V/±10% X7R Ceramic Chip Capacitor", Manufacturer="Samsung Electro-Mechanics"
C12 C13: library part P5154-ND, "330 µF 25 V Aluminum Electrolytic Capacitors Radial, Can 2000 Hrs @ 85°C"
C14 C15: library part C330C224K1R5TA, "0.22 µF ±10% 100V Ceramic Capacitor X7R Radial"
C21 C22 C23 C24: library part TAP105M035SCS, "1 µF Conformal Coated Tantalum Capacitors 35 V Radial 8Ohm"
C28 C29: library part RCE5C1H5R0C0M1H03A, "5 pF ±0.25pF 50V Ceramic Capacitor C0G, NP0 Radial"
CN1: ".050\"[1.27mm] Contact Centers, Male Header", Manufacturer="Sullins Connector Solutions, Inc."
CN2: library part ADDB9P, "9 Position D-Sub Plug, Male Pins Connector"
CN4 CN5: "MC 1,5/2G-3,81 Pluggable Terminal Block 2 Pos 3.81mm pitch Through Hole Header", Manufacturer="Phoenix Contact"
CN6: library part 180SH-EN
CN7: "USB-C Receptacle, Right-Angle, Surface Mount, Top Mount, Center Height 5.9mm, Single Row, 16 Circuits", Manufacturer=Molex
D1 D2: library part UF4002, "Diode 100 V 1A Through Hole DO-41"
D3: library part 1N4148, "Diode 100 V 200mA Through Hole DO-35"
FL1: "Common Mode Filter", Manufacturer=TDK
LCD1: library part LCM-S01602DTR/M, "Character Display Module Reflective 5 x 8 Dots TN - Twisted Nematic Without Backlight Parallel 66.00mm x 26.00mm x 6.50mm"
LED1 LED2: library part 150121M153000, "Micro RGB SMD LED, Common Anode", Manufacturer="Wurth Elektronik"
Q1 Q2: "Bipolar (BJT) Transistor NPN 40 V 200 mA 300MHz 625 mW Through Hole TO-92-3"
Q3 Q4 Q9 Q10: "N-Channel 200 V 180mA (Ta) 700mW (Ta) Through Hole TO-92"
Q5 Q6: "N-Channel 100 V 23A (Tc) 45W (Tc) Surface Mount PowerPAK® SO-8"
R1: library part CFR-25JR-52-56K, "56 kOhms ±5% 0.25W, 1/4W Through Hole Resistor Axial Automotive AEC-Q200 Carbon Film"
R2 R3 R4 R5 R6 R15 R16 R17 R29 R30: library part CR0805-FX-1002ELF, "10.0k, 1%, 0.125W Thick Film Chip Resistor", Manufacturer=Bourns
R7: library part CRCW0603470RFKEAHP, "470 Ohms ±1% 0.333W, 1/3W Chip Resistor 0603 (1608 Metric) Automotive AEC-Q200, Pulse Withstanding Thick Film"
R8: library part CRCW06031M00FKEAHP, "1 MOhms ±1% 0.333W, 1/3W Chip Resistor 0603 (1608 Metric) Automotive AEC-Q200, Pulse Withstanding Thick Film"
R9: library part CR0805-FX-1201ELF, "1.2 kOhms ±1% 0.125W, 1/8W Chip Resistor 0805 (2012 Metric) Moisture Resistant Thick Film"
R10 R18 R19 R20 R21 R22 R23 R24 R25 R27 R28 R31: library part CR0805-FX-4421ELF, "4.42k, 1%, 0.125W Thick Film Chip Resistor", Manufacturer=Bourns
R11 R12 R13 R14 R33 R34: library part CR0805-FX-7500ELF, "750, 1%, 0.125W Thick Film Chip Resistor", Manufacturer=Bourns
R26: library part CF1/4CT52R153J, "15 kOhms ±5% 0.25W, 1/4W Through Hole Resistor Axial Carbon Film"
R35: library part PV36W103C01B00, "10 kOhms 0.5W, 1/2W PC Pins Through Hole Trimmer Potentiometer Cermet 25 Turn Top Adjustment"
R36 R37: library part CR0805-FX-5101ELF, "5.10k, 1%, 0.125W Thick Film Chip Resistor", Manufacturer=Bourns
S1 S2 S3 S4 S5 S6: "KSC Series Sealed Tact Switch for SMT", Manufacturer="C&K Components"
TP_3.3V TP_3.3VA TP_3.3VP TP_5.0VP TP_5V TP_12V TP_G1 TP_G2 TP_G3 TP_G12 TP_VBUS: library part TP3, "Test Point, Surface Mount, 3 mm", Manufacturer="Confederation College", PartNumber=N/A
U1: library part TM4C123GH6PM, "Microcontroller", Manufacturer="Texas Instruments"
U2 U10 U11: "250 mA, 3.3V Low Dropout Voltage Regulator", Manufacturer="Texas Instruments"
U3: library part LT1490CN8, "Standard (General Purpose) Amplifier 2 Circuit Rail-to-Rail 8-PDIP"
U4: library part 505-TMP35GT9Z-ND, "Temperature Sensor Analog, Local 10°C ~ 125°C 10mV/°C TO-92-3"
U5: library part PCF8574ADWR, "I/O Expander 8 I2C 100 kHz 16-SOIC"
U6: "Real Time Clock (RTC) IC Clock/Calendar 64B I2C, 2-Wire Serial 8-SOIC (0.154\", 3.90mm Width)"
U8: library part LT1081CN, "2/2 Transceiver Full RS232 16-PDIP"
U9: library part HIP4082IBZ, "Half Bridge, Full Bridge Driver DC Motors, General Purpose N-Channel MOSFET 16-SOIC"
U12: "TVS Diode Array - Low Capacitance ESD Protection", Manufacturer=Littelfuse
Y1: library part ABM3-16.000MHZ-B2-T, "16 MHz Miniature Ceramic SMD Crystal", Manufacturer="Abracon Corporation"
Y2: library part AB26TRB-32.768KHZ-T, "32.768 kHz Radial Can Crystal", Manufacturer="Abracon Corporation"

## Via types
v1: diameter 0.508, hole 0.254, Top Layer to Bottom Layer, tented both sides, 324 vias

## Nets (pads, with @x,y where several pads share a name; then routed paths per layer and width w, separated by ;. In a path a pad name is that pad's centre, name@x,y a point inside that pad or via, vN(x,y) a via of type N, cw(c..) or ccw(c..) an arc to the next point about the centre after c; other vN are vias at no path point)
3.3VP: C9.1 C10.1 C19.1 C30.1 Q9.2 Q10.2 R15.2 R16.2 R17.2 R27.2 R28.2 R31.2 TP_3.3VP.1 U5.16 U6.8 U10.5 | length 44.9
  Top Layer w0.254: Q9.2@47.135,22.045 47.102,22.012 47.102,15.687 Q10.2@47.07,15.655 54.306,15.655 v1(55.591,16.94) ; v1(53.048,41.782) 53.048,41.851 53.231,42.033 53.231,42.086 54.362,43.218 55.03,43.218 55.203,43.391 U10.5@55.203,43.591 55.203,46.25 v1(55.213,46.26) ; v1@55.225,46.272 55.225,50.347 55.678,50.8 TP_3.3VP.1@55.88,50.8
  Bottom Layer w0.254: R27.2@17.715,9.484 17.715,10.756 v1(17.78,10.821) ; v1(18.77,20.471) 18.84,20.401 19.623,20.401 C19.1@19.93,20.707 ; v1(22.184,21.68) 22.184,20.689 C10.1@22.216,20.657 ; v1(23.941,18.942) 23.956,18.957 R31.2@25.033,18.957 ; v1(26.412,6.9) 26.412,7.708 R15.2@26.44,7.736 ; v1(28.874,6.925) 28.874,7.785 R16.2@28.89,7.801 ; v1(31.308,6.969) 31.308,7.707 R17.2@31.335,7.734 ; R28.2@33.567,7.734 C9.1@35.932,7.734 ; C9.1@36.007,7.734 36.505,7.236 36.505,6.406 v1(37.328,5.584) ; v1(53.048,41.782) 53.048,38.513 v1(54.106,37.456) ; C30.1@54.029,17.032 55.43,17.032 55.523,16.94 v1(55.591,16.94)
+3.3V: C25.1 R3.1 R4.1 R5.2 R6.2 R8.2 R20.2 R21.2 TP_3.3V.1 U1.11 U1.26 U1.37 U1.42 U1.54 U11.5 | length 154.8
  Top Layer w0.254: v1(10.203,42.873) 11.657,41.419 v1(11.657,39.952) ; TP_3.3V.1@10.502,31.136 11.263,31.897 11.263,33.664 v1(11.74,34.141) ; v1(12.108,42.863) 12.14,42.895 13.072,42.895 14.195,41.772 14.426,41.772 14.43,41.769 14.851,41.769 14.855,41.772 v1(15.637,41.772) 16.404,41.006 v1(20.777,41.006) 20.777,41.074 21.07,41.367 U1.42@21.07,50.155 21.047,50.178 21.047,50.912 20.452,51.507 19.188,51.507 ; U1.26@14.595,55.13 14.618,55.153 16.092,55.153 16.58,55.641 16.58,56.234 17.004,56.657 v1(17.004,56.708) ; U1.37@18.57,50.155 18.593,50.178 18.593,50.912 19.188,51.507 ; U1.11@19.07,61.605 19.07,60.499 19.073,60.496 19.073,60.35 v1(19.198,60.225) ; v1(19.191,54.273) v1(19.191,56.739) 22.42,56.739 24.529,54.63 U1.54@26.045,54.63 ; v1(21.874,51.757) 19.438,51.757 19.188,51.507 ; v1(37.758,31.5) 39.968,31.5 v1(40.002,31.534)
  Bottom Layer w0.254: U11.5@7.877,43.702 9.374,43.702 v1(10.203,42.873) 12.098,42.873 v1(12.108,42.863) ; R5.2@10.318,34.925 R5.2@10.468,34.925 ; R4.1@10.502,39.768 10.686,39.952 v1(11.657,39.952) ; v1(11.74,34.141) 11.692,34.19 11.204,34.19 R5.2@10.468,34.925 ; R3.1@12.797,39.768 12.613,39.952 v1(11.657,39.952) ; v1(15.637,41.772) 15.637,43.159 C25.1@15.652,43.173 ; v1(19.191,54.273) 20.466,52.998 20.633,52.998 v1(21.874,51.757) ; v1(19.191,56.739) 19.159,56.708 v1(17.004,56.708) 16.987,56.724 16.987,57.964 17.091,58.068 17.091,58.085 19.198,60.191 v1(19.198,60.225) ; v1(20.777,41.006) 27.785,41.006 27.934,40.857 27.934,32.227 28.083,32.078 37.181,32.078 v1(37.758,31.5) ; v1(40.002,31.534) 45.735,31.534 R8.2@48.214,29.055 ; R6.2@41.914,25.022 48.005,25.022 48.214,25.231 R8.2@48.214,29.055 ; R21.2@54.052,8.258 54.45,8.656 54.847,8.656 56.279,10.087 R20.2@56.279,12.321 ; R20.2@56.279,12.416 56.374,12.321 57.641,12.321 57.79,12.469 57.79,28.907 57.641,29.055 R8.2@48.214,29.055 ; R5.2@10.468,34.925 10.866,35.323 10.866,35.473 11.657,36.264 v1(11.657,39.952)
+3.3VA: C1.1 C6.1 C20.1 R29.2 R35.2 TP_3.3VA.1 U1.2 U2.5 U3.8 U4.1 | length 24.4
  Top Layer w0.254: U1.2@23.57,61.605 23.57,62.841 v1(23.585,62.855) ; U3.8@28.973,34.473 28.973,35.762 v1(29.29,36.079) ; TP_3.3VA.1@56.721,47.84 56.923,47.84 57.354,47.409 v1(57.574,47.409)
  Bottom Layer w0.254: v1(23.585,62.855) 24.709,63.98 32.403,63.98 33.778,62.604 v1(33.778,60.125) ; v1(25.198,35.687) 25.247,35.638 25.691,35.638 25.908,35.42 R29.2@25.908,34.45 ; C20.1@63.347,51.891 63.347,50.692 v1(63.364,50.676) ; v1(65.027,51.895) 66.144,51.895 C1.1@66.222,51.817 ; U2.5@66.95,49.661 67.968,49.661 v1(67.981,49.674) ; C6.1@73.107,51.865 73.107,50.446 v1(73.114,50.438)
+5.0V: C8.1 C23.1 C27.1 CN3.2 CN4.1 CN6.5 LED1.4 Q1.3 TP_5V.1 U2.1 U2.3 U8.16 U11.1 U11.3 | length 168.1
  Top Layer w0.254: v1(4.043,43.17) 4.77,43.897 5.992,43.897 6.719,44.624 6.719,44.917 7.627,45.825 LED1.4@7.877,45.825 9.071,45.825 9.22,45.676 9.22,42.815 9.061,42.656 v1(9.061,39.351) ; v1(7.62,17.78) 7.257,18.143 7.257,32.32 7.406,32.469 v1(8.857,32.469) ; C23.1@38.606,53.486 38.704,53.584 v1(38.704,55.261) ; v1(43.67,57.224) 43.647,57.247 43.647,57.986 44.251,58.59 47.826,58.59 Q1.3@48.74,59.505 ; v1(59.536,15.964) 59.585,16.012 59.585,17.267 TP_5V.1@59.648,17.331 ; v1(64.695,60.606) 64.702,60.613 64.702,61.868 v1(64.709,61.875) ; U8.16@70.996,54.902 71.017,54.881 71.017,49.809 71.028,49.799 71.028,49.378 71.017,49.367 71.017,47.325 v1(71.038,47.304)
  Bottom Layer w0.254: v1(4.043,43.17) 4.091,43.218 4.444,43.218 4.927,43.702 U11.1@5.127,43.702 4.954,43.875 4.551,43.875 3.855,44.571 3.855,44.782 4.501,45.429 4.954,45.429 U11.3@5.127,45.602 4.927,45.602 4.754,45.775 4.754,45.975 4.481,46.248 4.481,60.263 5.339,61.121 7.484,61.121 CN6.5@7.583,61.22 ; v1@7.637,17.763 7.637,4.402 8.311,3.727 CN4.1@8.311,3.38 ; v1(8.857,32.469) 8.857,39.079 9.061,39.282 v1(9.061,39.351) ; v1(38.704,55.261) 38.752,55.213 38.919,55.213 38.98,55.152 44.467,55.152 44.616,55.301 44.616,56.976 44.467,57.125 43.946,57.125 43.896,57.175 43.719,57.175 v1(43.67,57.224) ; Q1.3@48.74,59.505 48.74,63.84 50.785,65.885 64.438,65.885 64.614,65.71 64.614,61.971 v1(64.709,61.875) ; v1(63.507,47.727) 64.226,48.446 64.226,52.696 63.875,53.048 62.645,53.048 62.183,53.51 62.183,59.45 62.332,59.598 63.688,59.598 v1(64.695,60.606) ; v1(63.791,46.875) 63.827,46.911 U2.3@65.05,46.911 ; U2.1@66.95,46.911 68.368,46.911 v1(68.369,46.91) ; U8.16@70.996,54.902 74.781,54.902 77.005,57.125 C27.1@77.08,57.125 77.446,56.759 79.956,56.759 86.044,62.847 86.044,64.031 86.034,64.041 C8.1@86.034,66.473
+5.0VP: C11.1 C17.1 LCD1.2 LED2.4 Q1.1 R24.2 R25.2 TP_5.0VP.1 U7.7 U10.1 U10.3 | length 54.5
  Top Layer w0.254: LCD1.2@39.248,68.626 39.166,68.543 39.166,64.865 39.315,64.717 43.8,64.717 43.949,64.568 43.949,61.756 Q1.1@46.2,59.505 ; LED2.4@41.987,10.487 42.055,10.555 v1(42.055,12.905) ; v1(46.132,57.681) 46.14,57.673 49.288,57.673 v1(49.297,57.665) ; v1(47.286,55.171) 47.286,51.377 v1(47.377,51.286) ; v1(50.64,47.562) 53.255,44.948 v1(54.394,44.948) ; TP_5.0VP.1@51.74,30.946 51.752,30.935 51.752,29.8 v1(51.764,29.788) ; v1(54.33,39.648) 54.379,39.696 54.379,39.817 55.203,40.641 U10.1@55.203,40.841 ; v1(57.099,39.665) 57.103,39.669 U10.3@57.103,40.841
  Bottom Layer w0.254: R24.2@31.838,18.957 R25.2@34.586,18.957 36.855,18.957 C11.1@36.905,19.007 36.943,19.045 v1(39.429,19.045) ; U7.7@34.435,16.294 U7.7@34.468,16.261 ; v1(46.132,57.681) 46.132,59.436 Q1.1@46.2,59.505 ; v1(47.286,55.171) 49.145,55.171 49.409,55.435 49.409,56.46 49.297,56.572 v1(49.297,57.665) ; v1(47.377,51.286) 47.446,51.286 47.694,51.535 48.664,51.535 49.258,50.941 49.258,50.054 50.64,48.672 v1(50.64,47.562) ; C17.1@53.099,44.931 54.377,44.931 v1(54.394,44.948)
+12V: C12.1 C13.1 C16.1 CN5.1 D1.A D2.A Q5.3 Q7.3 TP_12V.1 U9.2 U9.7 U9.12 | length 3
  Top Layer w0.254: TP_12V.1@78.579,3.068 79.189,3.678 v1(79.309,3.678)
  Bottom Layer w0.254: v1(92.394,10.183) 92.394,10.219 92.825,10.65 C16.1@92.825,12 ; U9.12@95.567,14.817 U9.12@95.62,14.817
AIN4: C2.1 R35.3 U1.64 | length 13.1
  Top Layer w0.254: U1.64@26.045,59.63 26.058,59.643 27.64,59.643 v1(27.653,59.657)
  Bottom Layer w0.254: v1(27.653,59.657) 27.686,59.624 28.209,59.624 C2.1@28.707,59.126 29.029,59.448 31.03,59.448 31.179,59.299 31.179,53.649 31.328,53.5 R35.3@33,53.5
AIN5: R1.2 U1.63 U3.1 | length 60.3
  Top Layer w0.254: v1(22.659,38.704) 22.669,38.714 22.669,42.119 v1(22.679,42.129) ; U1.63@26.045,59.13 29.823,59.13 29.972,58.981 v1(29.972,58.278) ; U3.1@28.973,26.853 28.928,26.898 28.928,28.151 29.076,28.3 40.122,28.3 40.699,28.877 R1.2@40.838,28.877
  Bottom Layer w0.254: v1(22.659,38.704) 22.659,30.236 26.042,26.853 U3.1@28.973,26.853 ; v1(22.679,42.129) 22.679,45.008 23.008,45.337 28.601,45.337 29.396,46.132 29.396,49.741 29.645,49.99 29.645,56.73 29.661,56.746 29.661,57.967 v1(29.972,58.278)
CONTRAST: LCD1.3 U7.1 | length 47.8
  Top Layer w0.254: v1@36.584,38.186 36.584,35.855 36.733,35.706 38.688,35.706 38.748,35.766 v1(38.817,35.766) ; v1(36.662,61.272) 36.708,61.318 LCD1.3@36.708,68.626 ; U7.1@37.008,23.881 38.344,25.216 38.344,25.816 v1(38.379,25.851)
  Bottom Layer w0.254: v1(36.599,38.201) 36.633,38.235 36.633,61.243 v1(36.662,61.272) ; v1(38.379,25.851) 38.817,26.289 v1(38.817,35.766)
GND: C1.2 C2.2 C3.2 C4.2 C5.2 C6.2 C7.2 C8.2 C9.2 C10.2 C11.2 C17.2 C18.2 C19.2 C20.2 C24.2 C25.2 C26.2 C27.2 C28.2 C29.2 C30.2 CN1.3 CN1.5 CN1.9 CN2.5 CN3.5 CN4.2 CN6.4 CN7.1 CN7.A1B12 CN7.B1A12 LCD1.1 Q2.1 Q3.1 Q4.1 R2.1 R18.1 R19.1 R30.1 R35.1 R36.1 R37.1 S1.1 S2.2 S3.2 S4.1 S5.1 S6.1 TP_G1.1 TP_G2.1 TP_G3.1 U1.3 U1.12 U1.27 U1.39 U1.55 U2.2 U3.4 U4.3 U5.1 U5.2 U5.3 U5.8 U6.4 U7.2 U7.5 U7.6 U8.15 U10.2 U11.2 U12.2 | length 116.7
  Top Layer w0.254: CN7.B1A12@10.092,21.457 10.161,21.388 v1(11.397,21.388) ; CN7.A1B12@10.092,27.857 10.442,27.857 11.24,28.654 v1(11.24,28.888) ; U1.27@14.595,54.63 16.27,54.63 v1(16.292,54.608) ; v1(18.565,60.277) 18.57,60.282 U1.12@18.57,61.605 ; v1(19.508,48.471) 19.547,48.51 19.547,50.132 U1.39@19.57,50.155 ; U1.3@23.07,61.605 23.077,61.598 23.077,60.295 v1(23.083,60.288) ; U1.55@26.045,55.13 U1.55@26.045,55.13 28.169,55.131 v1(28.17,55.132) ; TP_G2.1@51.74,27.344 51.857,27.228 v1(51.857,26.226) ; v1(56.144,39.318) 56.153,39.326 U10.2@56.153,40.841 ; v1(57.427,50.01) 57.427,50.235 57.79,50.598 TP_G1.1@57.79,50.8 ; TP_G3.1@59.595,24.291 59.595,23.233 v1(59.654,23.174) ; v1(76.055,54.93) 77.969,54.93 S2.2@78.055,55.015 ; v1(76.342,47.732) 78.408,47.732 S3.2@78.466,47.79 ; v1(87.656,51.842) 89.942,51.842 S4.1@90.1,52 ; v1(87.905,35.871) 87.946,35.913 v1(87.946,37.281) ; v1(87.97,41.966) 88.004,42 S5.1@90.1,42 ; v1(88.012,32.966) 88.046,33 S6.1@90,33 ; S1.1@90.1,60 90.325,60.225 v1(90.325,61.78)
  Bottom Layer w0.254: v1(3.434,24.735) 3.445,24.723 U12.2@4.542,24.723 ; U11.2@5.127,44.652 6.02,44.652 v1(6.025,44.647) ; v1(5.449,50.624) 5.449,49.625 6.615,48.459 C26.2@6.615,48.409 ; v1(14.974,11.67) 14.974,12.842 R37.1@14.979,12.847 ; R36.1@14.979,17.749 16.749,17.749 v1(16.798,17.798) ; v1(15.462,36.656) 15.503,36.697 C5.2@15.503,38.121 ; C25.2@15.652,44.823 15.652,47.513 v1(16.219,48.08) ; C4.2@18.276,38.136 18.276,36.758 v1(18.314,36.721) ; v1(18.652,19.027) 18.682,19.057 C19.2@19.93,19.057 19.98,19.007 C10.2@22.216,19.007 ; v1(20.665,36.656) 20.665,38.099 R2.1@20.73,38.164 ; v1(26.841,29.696) 26.86,29.715 R30.1@28.736,29.715 ; C2.2@28.707,57.476 28.782,57.401 v1(28.782,55.956) ; v1(34.623,9.331) 34.623,9.262 34.937,8.948 34.937,8.886 35.434,8.886 C9.2@35.932,9.384 ; C11.2@36.905,20.657 39.15,20.657 39.248,20.755 v1(39.316,20.755) ; v1(39.124,56.813) 40.348,56.813 R19.1@40.511,56.65 ; C3.2@39.879,24.902 39.879,26.18 v1(39.903,26.204) ; v1(40.254,42.915) 40.353,43.014 C18.2@40.353,44.922 ; C17.2@53.099,46.581 53.597,47.079 54.114,47.079 v1(54.195,47.16) ; v1(54.015,13.901) 54.015,15.368 C30.2@54.029,15.382 ; v1(59.654,23.174) 65.848,23.174 66,23.021 Q3.1@66,17.625 67.086,17.625 68.184,16.526 68.184,13.781 67.37,12.967 67.347,12.967 Q4.1@66,11.62 ; v1(61.188,52.968) 61.199,52.956 61.199,52.389 C20.2@61.697,51.891 ; U2.2@66,46.911 66,46.168 v1(66.157,46.011) ; C1.2@67.872,51.817 67.91,51.778 v1(68.926,51.778) ; R18.1@68.359,58.155 69.403,58.155 v1(69.547,58.299) ; v1(70.365,51.819) 71.412,51.819 C6.2@71.457,51.865 ; v1(74.741,68.576) 75.766,67.552 C7.2@75.766,66.521 ; C27.2@77.08,58.775 77.138,58.834 77.138,60.272 77.426,60.56 v1(78.227,60.56) ; CN2.5@87.478,69.532 87.478,66.679 C8.2@87.684,66.473 ; v1(87.656,51.842) 87.656,51.773 87.97,51.459 v1(87.97,41.966) 87.97,37.305 v1(87.946,37.281) ; v1@87.887,35.853 87.887,33.159 88.012,33.035 v1(88.012,32.966)
GND_12: C12.2 C13.2 C16.2 CN5.2 Q6.1 Q8.1 R26.1 TP_G12.1 U9.6 U9.8 | length 3.3
  Top Layer w0.254: v1(74.649,3.108) 74.689,3.068 TP_G12.1@76.224,3.068
  Bottom Layer w0.254: v1(91.172,13.674) 91.175,13.671 C16.2@91.175,12
I2C0SCL: Q10.1 R28.1 U1.47 U5.14 U6.6 | length 84
  Top Layer w0.254: U1.47@23.57,50.155 23.57,49.58 23.532,49.542 23.532,24.737 22.931,24.136 U6.6@22.931,23.966 24.188,23.966 v1(24.221,23.999) ; v1(24.221,21.86) 25.304,20.777 25.304,18.11 28.527,14.888 44.461,14.888 44.864,14.485 44.864,14.05 Q10.1@45.8,13.115 45.336,12.651 v1(45.336,11.143)
  Bottom Layer w0.254: v1(24.221,21.86) v1(24.221,23.999) ; U5.14@30.621,5.471 30.621,5.753 30.343,6.031 30.343,12.041 30.492,12.189 32.042,12.189 32.191,12.041 32.191,10.71 33.417,9.484 R28.1@33.567,9.484 33.567,10.498 33.626,10.556 44.75,10.556 v1(45.336,11.143)
I2C0SDA: Q9.1 R27.1 U1.48 U5.15 U6.5 | length 113.8
  Top Layer w0.254: U1.48@24.07,50.155 24.07,48.917 25.706,47.281 25.706,43.181 25.929,42.958 25.929,39.947 25.706,39.724 25.706,24.201 U6.5@25.471,23.966 27.021,23.966 v1(27.054,23.999) ; v1(26.152,1.845) 27.946,1.845 v1(28.036,1.935) ; v1(27.082,21.888) 27.082,18.175 27.231,18.027 44.387,18.027 Q9.1@45.865,19.505 ; v1(31.332,3.719) 33.142,3.719 33.291,3.867 33.291,5.341 U5.15@33.161,5.471
  Bottom Layer w0.254: R27.1@17.715,7.734 17.317,7.336 16.207,7.336 16.058,7.187 16.058,1.797 26.104,1.797 v1(26.152,1.845) ; v1(27.054,23.999) 27.054,21.916 v1(27.082,21.888) ; v1(28.036,1.935) 28.082,1.935 28.508,1.508 31.183,1.508 31.332,1.657 v1(31.332,3.719) ; U5.15@33.161,5.471 33.161,3.452 40.537,3.452 43.028,5.943 47.068,5.943 47.217,6.092 47.217,14.065 45.778,15.504 45.778,19.418 Q9.1@45.865,19.505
